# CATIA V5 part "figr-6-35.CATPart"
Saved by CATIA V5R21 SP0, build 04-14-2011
Part number: Part1
Bounding box of the stored display mesh (mm): x -40.3 to 40.3, y -45.975 to 45.975, z 0 to 40
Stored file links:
  D:\CATIA V5R21 E-RESOURCES\CATIA-V5R21\catia-v5r21-prt\c06-catia-v5r21-prt\c06-catia-v5r21-figr-6-35.CATPart
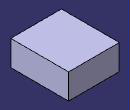
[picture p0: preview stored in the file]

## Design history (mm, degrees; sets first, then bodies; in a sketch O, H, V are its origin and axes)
Body1 (main body)
  Sketch1 on xy-plane, origin (0, 0, 0), H (1, 0, 0), V (0, 1, 0)
    line L1 (-40.2998, 45.9753) -> (40.2998, 45.9753)
    line L2 (40.2998, 45.9753) -> (40.2998, -45.9753)
    line L3 (40.2998, -45.9753) -> (-40.2998, -45.9753)
    line L4 (-40.2998, -45.9753) -> (-40.2998, 45.9753)
    axis line L5 (40.2998, -45.9753) -> (-40.2998, 45.9753)
    horizontal: L1 H, L3 H
    vertical: L2 V, L4 V
    midpoint: O L5
  Pad1: profile Sketch1, direction (0, 0, 1), length 40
